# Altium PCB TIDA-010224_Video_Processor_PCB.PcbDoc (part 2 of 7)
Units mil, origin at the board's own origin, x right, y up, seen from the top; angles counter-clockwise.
Board outline 2355.46 x 4164 mil, 10 copper layers (L1-Top Layer, L2-GND, L3-SIG1, L4-GND, L5-PWR, L6-PWR, L7-GND, L8-SIG2, L9-GND, L10-Bottom Layer), stack 62.2 mil thick; 508 components, 274 nets, 3619 pads, 705 vias.
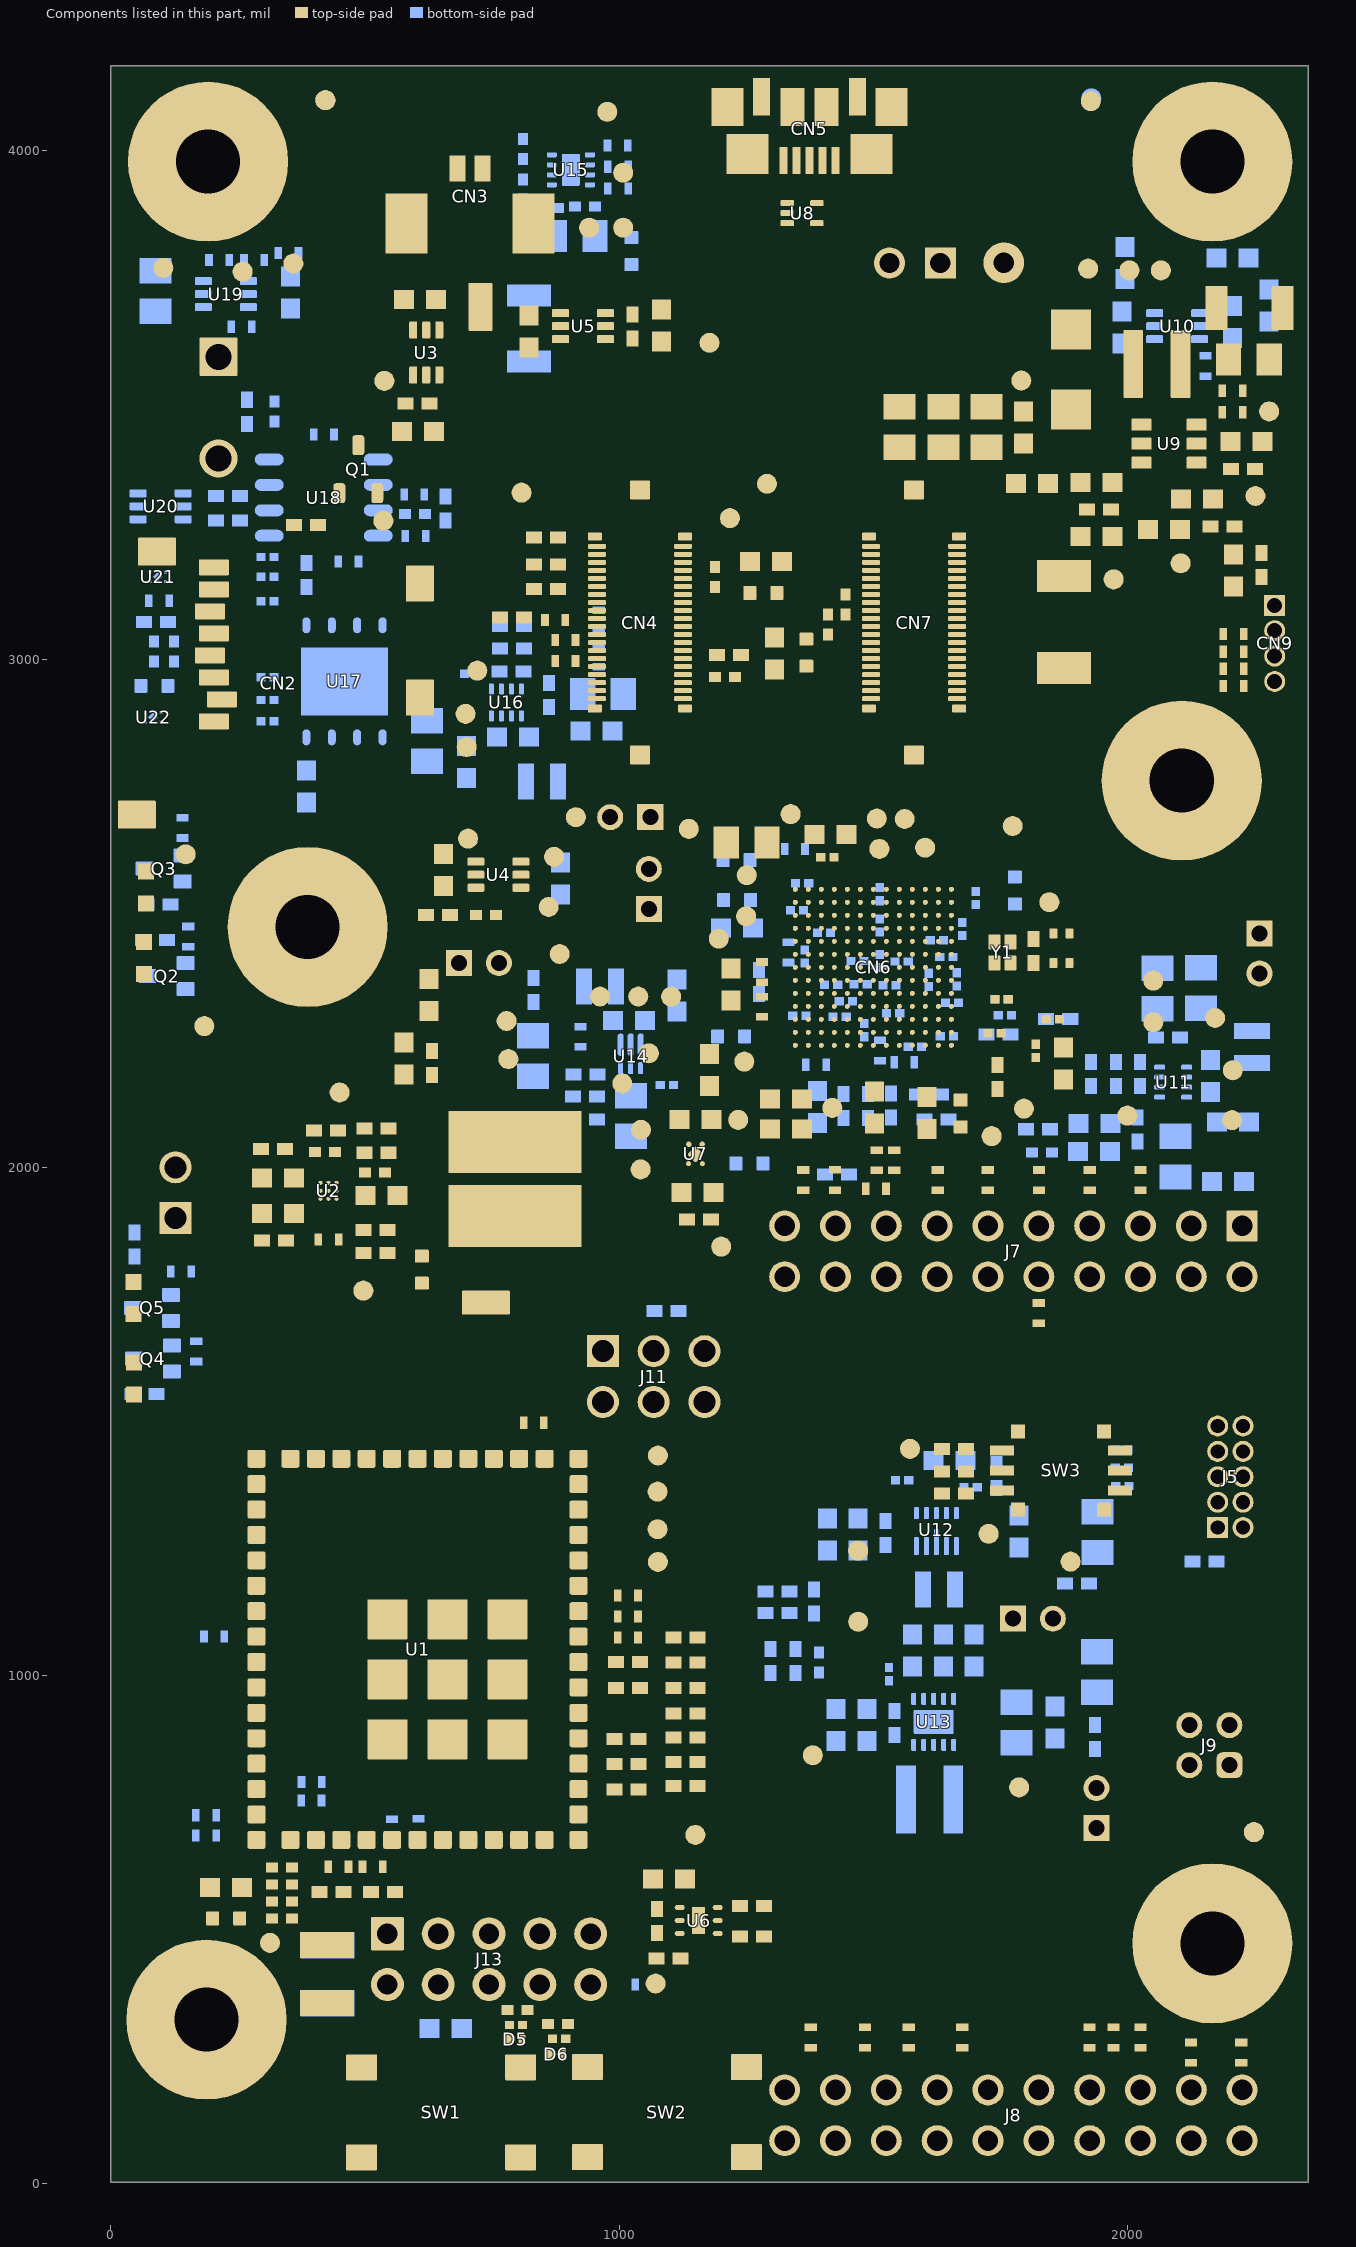
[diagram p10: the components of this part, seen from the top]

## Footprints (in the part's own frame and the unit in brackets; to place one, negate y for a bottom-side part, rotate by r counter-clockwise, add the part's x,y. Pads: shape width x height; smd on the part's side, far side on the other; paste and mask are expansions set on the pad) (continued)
2010 [mm] "Chip Capacitor, Body 5.08x2.54mm, IPC Medium Density"
  rect 1.6x2.7 smd: 1(-2.3,0) 2(2.3,0)
  silkscreen extent -3.42,-1.65 3.42,1.65, body extent -2.73,-1.45 2.73,1.45, height 1.66
0533980271 [mm] "Molex PicoBlade 2 pos from documents no. SD-53398-033 dated 2006-04-02"
  rect 0.8x1.3 smd: 1(-0.625,1.375) 2(0.625,1.375)
  rect 2.1x3 smd: 3(-3.175,-1.375) 4(3.175,-1.375)
  silkscreen extent -4.55,-3.17 4.57,2.29, body extent -3.86,-2.44 3.79,1.76, height 4.8
AssemblyNote [mil] "Assembly Note"
AssemblyNoteLabel [mil] "Assembly Note for PCB Labels"
BoosterPack_40pin_J1J3 [mm] "Receptacle, 2.54mm, 10x2, TH"
  rrect6% 1.55x1.55 hole 1.02: 1(1.27,11.43)
  round 1.55 hole 1.02: 2(1.27,8.89) 3(1.27,6.35) 4(1.27,3.81) 5(1.27,1.27) 6(1.27,-1.27) 7(1.27,-3.81) 8(1.27,-6.35) 9(1.27,-8.89) 10(1.27,-11.43) 21(-1.27,11.43) 22(-1.27,8.89) 23(-1.27,6.35) 24(-1.27,3.81) 25(-1.27,1.27) 26(-1.27,-1.27) 27(-1.27,-3.81) 28(-1.27,-6.35) 29(-1.27,-8.89) 30(-1.27,-11.43)
  silkscreen extent -2.48,-12.95 2.48,12.95, body extent -2.48,-12.95 2.48,12.95, height 8.51
BoosterPack_40pin_J2J4 [mm] "Receptacle, 2.54mm, 10x2, TH"
  round 1.55 hole 1.02: 11(-1.27,-11.43) 12(-1.27,-8.89) 13(-1.27,-6.35) 14(-1.27,-3.81) 15(-1.27,-1.27) 16(-1.27,1.27) 17(-1.27,3.81) 18(-1.27,6.35) 19(-1.27,8.89) 20(-1.27,11.43) 31(1.27,-11.43) 32(1.27,-8.89) 33(1.27,-6.35) 34(1.27,-3.81) 35(1.27,-1.27) 36(1.27,1.27) 37(1.27,3.81) 38(1.27,6.35) 39(1.27,8.89) 40(1.27,11.43)
  silkscreen extent -2.48,-12.95 2.48,12.95, body extent -2.48,-12.95 2.48,12.95, height 8.51
CE_Mark_5mm [mil] "Minimum text height for CE Mark"
  silkscreen extent -138,-98 138,98
CUI_CMA-6542TF-K [mil] "SMD, 2-Leads, Dia 9.9mm"
  rect 121.67x262.28 smd: 1(-72.65,0) 2(72.65,0)
  silkscreen extent -195,-195 195,195, body extent -191,-191 191,191, height 272
D0008A_N [mm] "SOIC, 8-Leads, Body 4.9x3.9mm, Pitch 1.27mm, IPC Medium Density"
  oval 1.45x0.6 smd: 1(-2.725,1.905) 2(-2.725,0.635) 3(-2.725,-0.635) 4(-2.725,-1.905) 5(2.725,-1.905) 6(2.725,-0.635) 7(2.725,0.635) 8(2.725,1.905)
  silkscreen extent -3.3,-2.5 0.9,2.5, body extent -3,-2.45 3,2.45, height 1.63
DBV0006A_N [mm] "SOT23, 6-Leads, Body 2.9x1.6mm, Pitch 0.95mm, Lead Span 2.8mm, IPC Medium Density"
  rrect17% 1x0.6 smd: 1(-1.375,0.95) 2(-1.375,0) 3(-1.375,-0.95) 4(1.375,-0.95) 5(1.375,0) 6(1.375,0.95)
  silkscreen extent -1.68,-1.55 0.5,1.55, body extent -1.42,-1.46 1.42,1.46, height 1.12
DCK0006A_N [mm] "SOT23, 6-Leads, Body 2x1.3mm, Pitch 0.65mm, Lead Span 2.1mm, IPC Medium Density"
  rrect25% 0.85x0.4 smd: 1(-1.125,0.65) 2(-1.125,0) 3(-1.125,-0.65) 4(1.125,-0.65) 5(1.125,0) 6(1.125,0.65)
  silkscreen extent -1.5,-1.09 0.51,1.09, body extent -1.14,-1 1.14,1, height 0.95
DFE201610E [mm] "MuRata"
  rect 0.8x1.8 smd: 1(0.8,0) 2(-0.8,0)
  body extent -1.1,-0.9 1.1,0.9, height 1
DLA0010A [mm] "VQFN-HR-10"
  rrect40% 0.6x0.25 smd: 1(-0.9,1) 2(-0.9,0.5) 3(-0.9,0) 4(-0.9,-0.5) 5(-0.9,-1)
  rrect40% 0.9x0.25 smd: 6(0.75,-1) 7(0.75,-0.5) 9(0.75,0.5) 10(0.75,1)
  rrect40% 1.3x0.25 smd paste-1: 8(0.55,0)
  silkscreen extent -1,-1.65 1,1.9, body extent -1,-1.5 1,1.5, height 1
DLC0008A [mm] "VSON-HR-8"
  rrect40% 0.55x0.25 smd: 1(-0.675,0.75) 2(-0.675,0.25) 3(-0.675,-0.25) 4(-0.675,-0.75) 5(0.675,-0.75) 6(0.675,-0.25) 7(0.675,0.25) 8(0.675,0.75)
  silkscreen extent -0.75,-1.15 0.75,1.15, body extent -0.8,-1.05 0.8,1.05, height 1.02
DMQ0006A [mm] "6-pin VSON"
  rrect40% 0.6x0.25 smd paste+0: 1(-0.65,0.5) 2(-0.65,0) 3(-0.65,-0.5)
  rrect67% 1.1x0.3 smd paste-0.15 mask-0.025: 4(0.52,-0.5) 5(0.525,0) 6(0.525,0.5)
  rrect50% 0.85x0.2 on Bottom Paste: 4(0.525,-0.5) 5(0.525,0) 6(0.525,0.5)
  silkscreen extent -0.75,-0.9 0.75,0.9, body extent -0.75,-0.75 0.75,0.75, height 1
DNP0006A [mm] "DFN-6 2x2mm"
  oval 0.5x0.25 smd: 1(-0.95,0.65) 2(-0.95,0) 3(-0.95,-0.655) 4(0.95,-0.65) 5(0.95,0) 6(0.95,0.65)
  rect 0.65x1.35 smd paste-0.5: 7(0,0)
  silkscreen extent -1.12,-1.15 1.12,1.15, body extent -1,-1 1,1, height 0.64
DPW0004A#1 [mm] "PX2SON"
  rect 0.15x0.15 smd mask+0.05: 1(-0.39,0.24) 2(-0.39,-0.24) 3(0.39,-0.24) 4(0.39,0.24)
  rect 0.35x0.35 smd rot 135 paste-0.055 mask-0.05: 5(0,0)
  L1-Top Layer region: -0.55,0.08 -0.588,0.088 -0.621,0.109 -0.642,0.142 -0.65,0.18 -0.65,0.18 -0.65,0.3 -0.642,0.338 -0.621,0.371 -0.588,0.392 -0.55,0.4 -0.55,0.4 -0.13,0.4 -0.13,0.269 -0.319,0.08
  L1-Top Layer region: 0.13,-0.4 0.13,-0.269 0.319,-0.08 0.55,-0.08 0.588,-0.088 0.621,-0.109 0.642,-0.142 0.65,-0.18 0.65,-0.18 0.65,-0.3 0.642,-0.338 0.621,-0.371 0.588,-0.392 0.55,-0.4 0.55,-0.4
  L1-Top Layer region: 0.319,0.08 0.13,0.269 0.13,0.4 0.55,0.4 0.588,0.392 0.621,0.371 0.642,0.338 0.65,0.3 0.65,0.3 0.65,0.18 0.642,0.142 0.621,0.109 0.588,0.088 0.55,0.08 0.55,0.08 0.55,0.08
  L1-Top Layer region: -0.55,-0.4 -0.588,-0.392 -0.621,-0.371 -0.642,-0.338 -0.65,-0.3 -0.65,-0.3 -0.65,-0.18 -0.642,-0.142 -0.621,-0.109 -0.588,-0.088 -0.55,-0.08 -0.55,-0.08 -0.319,-0.08 -0.13,-0.269 -0.13,-0.4
  silkscreen extent -0.6,-0.6 0.6,0.6, body extent -0.42,-0.42 0.42,0.42, height 0.41
DPW0004A#2 [mm] "PX2SON"
  rect 0.15x0.15 smd mask+0: 1(-0.39,0.24) 2(-0.39,-0.24) 3(0.39,-0.24) 4(0.39,0.24)
  rect 0.35x0.35 smd rot 135 paste-0.055 mask-0.05: 5(0,0)
  L1-Top Layer region: -0.55,-0.4 -0.588,-0.392 -0.621,-0.371 -0.642,-0.338 -0.65,-0.3 -0.65,-0.3 -0.65,-0.18 -0.642,-0.142 -0.621,-0.109 -0.588,-0.088 -0.55,-0.08 -0.55,-0.08 -0.319,-0.08 -0.13,-0.269 -0.13,-0.4
  L1-Top Layer region: 0.319,0.08 0.13,0.269 0.13,0.4 0.55,0.4 0.588,0.392 0.621,0.371 0.642,0.338 0.65,0.3 0.65,0.3 0.65,0.18 0.642,0.142 0.621,0.109 0.588,0.088 0.55,0.08 0.55,0.08 0.55,0.08
  L1-Top Layer region: 0.13,-0.4 0.13,-0.269 0.319,-0.08 0.55,-0.08 0.588,-0.088 0.621,-0.109 0.642,-0.142 0.65,-0.18 0.65,-0.18 0.65,-0.3 0.642,-0.338 0.621,-0.371 0.588,-0.392 0.55,-0.4 0.55,-0.4
  L1-Top Layer region: -0.55,0.08 -0.588,0.088 -0.621,0.109 -0.642,0.142 -0.65,0.18 -0.65,0.18 -0.65,0.3 -0.642,0.338 -0.621,0.371 -0.588,0.392 -0.55,0.4 -0.55,0.4 -0.13,0.4 -0.13,0.269 -0.319,0.08
  silkscreen extent -0.6,-0.6 0.6,0.6, body extent -0.42,-0.42 0.42,0.42, height 0.41
DPY0002A [mm] "X1SON-2"
  rrect57% 0.35x0.6 smd paste-0.5 mask-0.05: 1(-0.325,0) 2(0.325,0)
  rrect33% 0.3x0.5 on Top Paste: 1S(-0.35,0) 2S(0.35,0)
  silkscreen extent -0.85,-0.02 -0.8,0.02, body extent -0.5,-0.3 0.5,0.3, height 0.45
DQN0004A-MFG [mm] "SON, 0.65mm pitch"
  round 0.279 smd paste-1000 mask-1000: 1(-0.505,0.33) 2(-0.505,-0.33)
  round 0.251 smd paste-1000 mask-1000: 3(0.459,-0.346) 4(0.459,0.346)
  rrect17% 0.58x0.58 smd rot 135 paste-1000 mask-1000: 5(0,0)
  L1-Top Layer region: -0.66,0.485 -0.2,0.485 -0.2,0.385 -0.41,0.175 -0.66,0.175
  L1-Top Layer region: 0.66,-0.485 0.2,-0.485 0.2,-0.385 0.41,-0.175 0.66,-0.175
  L1-Top Layer region: 0.66,0.485 0.2,0.485 0.2,0.385 0.41,0.175 0.66,0.175
  L1-Top Layer region: -0.66,-0.485 -0.2,-0.485 -0.2,-0.385 -0.41,-0.175 -0.66,-0.175
  silkscreen extent -0.57,-0.9 0.53,1.4, body extent -0.76,-0.63 0.76,0.63, height 0.25
DRL0005A [mm] "SOTFL, 5-Flat Leads, Body 1.2x1.6x0.6mm, Pitch 0.5mm, TI recommended"
  rrect33% 0.67x0.3 smd: 1(-0.74,0.5) 2(-0.74,0) 3(-0.74,-0.5) 4(0.74,-0.5) 5(0.74,0.5)
  silkscreen extent -0.9,-0.95 0.5,0.95, body extent -0.85,-0.85 0.85,0.85, height 0.62
DSG0008A [mm] "SON, 8-Leads, Body 2x2mm, Pitch 0.5mm, Thermal Pad 1.6x0.9mm, TI Recommended"
  rrect40% 0.5x0.25 smd: 1(-0.95,0.75) 2(-0.95,0.25) 3(-0.95,-0.25) 4(-0.95,-0.75) 5(0.95,-0.75) 6(0.95,-0.25) 7(0.95,0.25) 8(0.95,0.75)
  rrect14% 0.9x0.7 on Bottom Paste: 9(0,-0.45) 9(0,0.45)
  rrect11% 0.9x1.6 smd paste-0.45: 9(0,0)
  silkscreen extent -1.07,-1.15 1.07,1.15, body extent -1,-1 1,1, height 0.77
DSK0010A [mm] "SON, 10-Leads, Body 2.5x2.5mm, Pitch 0.5mm, Thermal Pad 2x1.2mm - ADI"
  rrect40% 0.6x0.25 smd: 1(-1.15,1) 2(-1.15,0.5) 3(-1.15,0) 4(-1.15,-0.5) 5(-1.15,-1) 6(1.15,-1) 7(1.15,-0.5) 8(1.15,0) 9(1.15,0.5) 10(1.15,1)
  rrect11% 1.13x0.89 on Bottom Paste: 11(0,-0.545) 11(0,0.545)
  rrect8% 1.2x2 smd paste-0.6: 11(0,0)
  silkscreen extent -1.3,-1.45 1.3,1.45, body extent -1.25,-1.25 1.25,1.25, height 0.8
FCC_disclaimer [mil]
Fiducial10-20 [mm]
  round 1 smd mask+0.5: 1(0,0)
  L1-Top Layer keep-out circle w1.178: c0,0 r0.5
FP-8Q-24.000MEIV-T_SMD-4-MFG [mm]
  rrect17% 0.75x0.6 smd paste+0 mask+0: 1(-0.525,-0.4) 2(0.525,-0.4) 3(0.525,0.4) 4(-0.525,0.4)
  silkscreen extent -1.22,-1.19 1.22,0.67, body extent -1,-0.8 1,0.8, height 0.25
FP-430152070826_SMT_TACT-MFG [mm]
  rrect8% 1.55x1.3 smd paste+0 mask+0: 1(-3.975,2.25) 2(-3.975,-2.25) 3(3.975,2.25) 4(3.975,-2.25)
  silkscreen extent -5.47,-3.2 3.2,3.2, body extent -4.85,-3.3 4.85,3.3, height 0.25
FP-693071010811_CONN_SMT_MEMORY-MFG [mm]
  rrect13% 0.8x1.5 smd paste+0 mask+0: 1(1.94,-3.1) 2(0.84,-2.7) 3(-0.26,-3.1) 4(-1.36,-3.3) 5(-2.46,-3.1) 6(-3.56,-3.3) 7(-4.66,-3.1) 8(-5.76,-3.1)
  rrect7% 1.4x1.9 smd paste+0 mask+0: 9(-6.55,-5.95) 9(6.6,-6.95)
  rrect7% 1.8x1.4 smd paste+0 mask+0: 10(-4.95,7.2) 10(0.75,7.2)
  silkscreen extent -7.12,-8.11 7.12,7.7, body extent -7.35,-8 7.4,8, height 0.25
FP-BLM18KG121TN1D_0603-MFG [mm] "0603 from SM-752 data"
  rrect15% 0.65x0.7 smd paste+0 mask+0: 1(-0.675,0) 2(0.675,0)
  silkscreen extent -0.87,-0.8 0.87,0.8, body extent -1.1,-0.58 1.1,0.58, height 0.25
FP-GRM1555C1H8R2BA01D_0402-MFG [mm] "0402 from SM-752 data"
  rrect25% 0.4x0.5 smd paste+0 mask+0: 1(-0.4,0) 2(0.4,0)
  silkscreen extent -0.53,-0.65 0.53,0.65, body extent -0.7,-0.38 0.7,0.38, height 0.25
FP-NTS4001NT1G_SC-70-MFG [mm]
  rrect14% 0.9x0.7 smd paste+0 mask+0: 1(-0.95,0.65) 2(-0.95,-0.65) 3(0.95,0)
  silkscreen extent -0.13,-1.1 0.67,1.1, body extent -0.63,-1 0.63,1, height 1
FP-OA7000_BGA169-IPC_C [mm]
  round 0.255 smd paste+0 mask+0: A1(-3.9,3.9) A2(-3.25,3.9) A3(-2.6,3.9) A4(-1.95,3.9) A5(-1.3,3.9) A6(-0.65,3.9) A7(0,3.9) A8(0.65,3.9) A9(1.3,3.9) A10(1.95,3.9) A11(2.6,3.9) A12(3.25,3.9) A13(3.9,3.9) B1(-3.9,3.25) B2(-3.25,3.25) B3(-2.6,3.25) B4(-1.95,3.25) B5(-1.3,3.25) B6(-0.65,3.25) B7(0,3.25) B8(0.65,3.25) B9(1.3,3.25) B10(1.95,3.25) B11(2.6,3.25) B12(3.25,3.25) B13(3.9,3.25) C1(-3.9,2.6) C2(-3.25,2.6) C3(-2.6,2.6) C4(-1.95,2.6) C5(-1.3,2.6) C6(-0.65,2.6) C7(0,2.6) C8(0.65,2.6) C9(1.3,2.6) C10(1.95,2.6) C11(2.6,2.6) C12(3.25,2.6) C13(3.9,2.6) D1(-3.9,1.95) D2(-3.25,1.95) D3(-2.6,1.95) D4(-1.95,1.95) D5(-1.3,1.95) D6(-0.65,1.95) D7(0,1.95) D8(0.65,1.95) D9(1.3,1.95) D10(1.95,1.95) D11(2.6,1.95) D12(3.25,1.95) D13(3.9,1.95) E1(-3.9,1.3) E2(-3.25,1.3) E3(-2.6,1.3) E4(-1.95,1.3) E5(-1.3,1.3) E6(-0.65,1.3) E7(0,1.3) E8(0.65,1.3) E9(1.3,1.3) E10(1.95,1.3) E11(2.6,1.3) E12(3.25,1.3) E13(3.9,1.3) F1(-3.9,0.65) F2(-3.25,0.65) F3(-2.6,0.65) F4(-1.95,0.65) F5(-1.3,0.65) F6(-0.65,0.65) F7(0,0.65) F8(0.65,0.65) F9(1.3,0.65) F10(1.95,0.65) F11(2.6,0.65) F12(3.25,0.65) F13(3.9,0.65) G1(-3.9,0) G2(-3.25,0) G3(-2.6,0) G4(-1.95,0) G5(-1.3,0) G6(-0.65,0) G7(0,0) G8(0.65,0) G9(1.3,0) G10(1.95,0) G11(2.6,0) G12(3.25,0) G13(3.9,0) H1(-3.9,-0.65) H2(-3.25,-0.65) H3(-2.6,-0.65) H4(-1.95,-0.65) H5(-1.3,-0.65) H6(-0.65,-0.65) H7(0,-0.65) H8(0.65,-0.65) H9(1.3,-0.65) H10(1.95,-0.65) H11(2.6,-0.65) H12(3.25,-0.65) H13(3.9,-0.65) J1(-3.9,-1.3) J2(-3.25,-1.3) J3(-2.6,-1.3) J4(-1.95,-1.3) J5(-1.3,-1.3) J6(-0.65,-1.3) J7(0,-1.3) J8(0.65,-1.3) J9(1.3,-1.3) J10(1.95,-1.3) J11(2.6,-1.3) J12(3.25,-1.3) J13(3.9,-1.3) K1(-3.9,-1.95) K2(-3.25,-1.95) K3(-2.6,-1.95) K4(-1.95,-1.95) K5(-1.3,-1.95) K6(-0.65,-1.95) K7(0,-1.95) K8(0.65,-1.95) K9(1.3,-1.95) K10(1.95,-1.95) K11(2.6,-1.95) K12(3.25,-1.95) K13(3.9,-1.95) L1(-3.9,-2.6) L2(-3.25,-2.6) L3(-2.6,-2.6) L4(-1.95,-2.6) L5(-1.3,-2.6) L6(-0.65,-2.6) L7(0,-2.6) L8(0.65,-2.6) L9(1.3,-2.6) L10(1.95,-2.6) L11(2.6,-2.6) L12(3.25,-2.6) L13(3.9,-2.6) M1(-3.9,-3.25) M2(-3.25,-3.25) M3(-2.6,-3.25) M4(-1.95,-3.25) M5(-1.3,-3.25) M6(-0.65,-3.25) M7(0,-3.25) M8(0.65,-3.25) M9(1.3,-3.25) M10(1.95,-3.25) M11(2.6,-3.25) M12(3.25,-3.25) M13(3.9,-3.25) N1(-3.9,-3.9) N2(-3.25,-3.9) N3(-2.6,-3.9) N4(-1.95,-3.9) N5(-1.3,-3.9) N6(-0.65,-3.9) N7(0,-3.9) N8(0.65,-3.9) N9(1.3,-3.9) N10(1.95,-3.9) N11(2.6,-3.9) N12(3.25,-3.9) N13(3.9,-3.9)
  silkscreen extent -5.55,-5 5,5, body extent -5.1,-5.1 5.1,5.1, height 0.25
FP-XAL4030-472MEC_SMD2-MFG [mm]
  rrect10% 0.98x3.4 smd paste+0 mask+0: 1(-1.185,0) 2(1.185,0)
  silkscreen extent -2.15,-2.15 2.15,2.15, body extent -2,-2 2,2, height 3.1
Harwin_M22-2510205 [mm] "Header, 2mm, 2x1, TH"
  rect 1.3x1.3 hole 0.8: 1(-1,0)
  round 1.3 hole 0.8: 2(1,0)
  silkscreen extent -2,-1.5 2,1, body extent -2,-1 2,1, height 5
Hirose_FX12B-40P-0_4SV [mm] "Plug, 0.4 mm, 20x2, SMT"
  rrect43% 0.9x0.23 smd paste-0.23: 1(-2.15,3.8) 2(2.15,3.8) 3(-2.15,3.4) 4(2.15,3.4) 5(-2.15,3) 6(2.15,3) 7(-2.15,2.6) 8(2.15,2.6) 9(-2.15,2.2) 10(2.15,2.2) 11(-2.15,1.8) 12(2.15,1.8) 13(-2.15,1.4) 14(2.15,1.4) 15(-2.15,1) 16(2.15,1) 17(-2.15,0.6) 18(2.15,0.6) 19(-2.15,0.2) 20(2.15,0.2) 21(-2.15,-0.2) 22(2.15,-0.2) 23(-2.15,-0.6) 24(2.15,-0.6) 25(-2.15,-1) 26(2.15,-1) 27(-2.15,-1.4) 28(2.15,-1.4) 29(-2.15,-1.8) 30(2.15,-1.8) 31(-2.15,-2.2) 32(2.15,-2.2) 33(-2.15,-2.6) 34(2.15,-2.6) 35(-2.15,-3) 36(2.15,-3) 37(-2.15,-3.4) 38(2.15,-3.4) 39(-2.15,-3.8) 40(2.15,-3.8)
  rrect25% 0.7x0.4 smd paste-0.23: MP1(-2.25,4.3) MP2(2.25,4.3) MP3(-2.25,-4.3) MP4(2.25,-4.3)
  rrect11% 1x0.95 smd paste-1: MP5(0,6.625) MP6(0,-6.625)
  rrect33% 0.7x0.3 on Top Paste paste-0.23: ""(-2.25,-4.3) ""(-2.25,4.3) ""(2.25,-4.3) ""(2.25,4.3)
  rrect50% 0.9x0.2 on Top Paste paste-0.23: ""(-2.15,-3.8) ""(-2.15,-3.4) ""(-2.15,-3) ""(-2.15,-2.6) ""(-2.15,-2.2) ""(-2.15,-1.8) ""(-2.15,-1.4) ""(-2.15,-1) ""(-2.15,-0.6) ""(-2.15,-0.2) ""(-2.15,0.2) ""(-2.15,0.6) ""(-2.15,1) ""(-2.15,1.4) ""(-2.15,1.8) ""(-2.15,2.2) ""(-2.15,2.6) ""(-2.15,3) ""(-2.15,3.4) ""(-2.15,3.8) ""(2.15,-3.8) ""(2.15,-3.4) ""(2.15,-3) ""(2.15,-2.6) ""(2.15,-2.2) ""(2.15,-1.8) ""(2.15,-1.4) ""(2.15,-1) ""(2.15,-0.6) ""(2.15,-0.2) ""(2.15,0.2) ""(2.15,0.6) ""(2.15,1) ""(2.15,1.4) ""(2.15,1.8) ""(2.15,2.2) ""(2.15,2.6) ""(2.15,3) ""(2.15,3.4) ""(2.15,3.8)
  rrect11% 0.9x0.95 on Top Paste paste-0.23: ""(0,-6.625) ""(0,6.625)
  body extent -2.45,-6.89 2.45,6.9, height 1.34
Hirose_ZX62R-B-5P [mm] "Hirose"
  rect 1.35x0.4 smd: 1(-2.68,1.3) 2(-2.68,0.65) 3(-2.68,0) 4(-2.68,-0.65) 5(-2.68,-1.3)
  rect 2x2.1 smd: 6(-2.35,-3.1) 7(-2.35,3.1)
  rect 1.9x1.6 smd: 8(0,-4.1) 13(0,4.1)
  rect 1.88x0.85 smd: 9(0.495,-2.4) 12(0.495,2.4)
  rect 1.9x1.2 smd: 10(0,-0.85) 11(0,0.85)
  silkscreen extent -4,-3.67 1.7,3.67, body extent -2.57,-3.48 2.11,3.45, height 2.65
Keystone5000 [mil] "For Keystone 500x miniature loop terminals"
  round 80 hole 40: 1(0,0)
  silkscreen extent -52,-52 52,52, body extent -49,-49 49,49, height 182
Keystone_1902C [mil] "Hex Standoff, 4-40 threaded, nylon"
  round 1 on Mech4: 0(0,0)
  body extent -145,-126 146,126, height 501
Label_650x200 [mil] "Thermal Transfer Label"
  round 1 on Mech14: 0(0,0)
  silkscreen extent -325,-100 325,100, body extent -325,-100 325,100, height 1
MON0063A [mm] "QFM"
  rrect22% 0.9x0.9 smd paste-0.05 mask+0.05: 1(-11.774,9.524) 2(-11.774,8.255) 3(-11.774,6.985) 4(-11.774,5.715) 5(-11.774,4.445) 6(-11.774,3.175) 7(-11.774,1.905) 8(-11.774,0.635) 9(-11.774,-0.635) 10(-11.774,-1.905) 11(-11.774,-3.175) 12(-11.774,-4.445) 13(-11.774,-5.715) 14(-11.774,-6.985) 15(-11.774,-8.255) 16(-11.774,-9.524) 17(-10.074,-9.524) 18(-8.804,-9.524) 19(-7.534,-9.524) 20(-6.264,-9.524) 21(-4.994,-9.524) 22(-3.724,-9.524) 23(-2.454,-9.524) 24(-1.184,-9.524) 25(0.086,-9.524) 26(1.356,-9.524) 27(2.626,-9.524) 28(4.326,-9.524) 29(4.326,-8.255) 30(4.326,-6.985) 31(4.326,-5.715) 32(4.326,-4.445) 33(4.326,-3.175) 34(4.326,-1.905) 35(4.326,-0.635) 36(4.326,0.635) 37(4.326,1.905) 38(4.326,3.175) 39(4.326,4.445) 40(4.326,5.715) 41(4.326,6.985) 42(4.326,8.255) 43(4.326,9.524) 44(2.626,9.524) 45(1.356,9.524) 46(0.086,9.524) 47(-1.184,9.524) 48(-2.454,9.524) 49(-3.724,9.524) 50(-4.994,9.524) 51(-6.264,9.524) 52(-7.534,9.524) 53(-8.804,9.524) 54(-10.074,9.524)
  rrect11% 0.89x0.89 on Top Paste: 55(-8.774,3.95) 55(-7.674,3.95) 56(-8.774,0.95) 56(-8.774,2.05) 56(-7.674,0.95) 56(-7.674,2.05) 57(-8.774,-2.05) 57(-8.774,-0.95) 57(-7.674,-2.05) 57(-7.674,-0.95) 58(-5.774,3.95) 58(-5.774,5.05) 58(-4.674,3.95) 58(-4.674,5.05) 59(-5.774,0.95) 59(-5.774,2.05) 59(-4.674,0.95) 59(-4.674,2.05) 60(-5.774,-2.05) 60(-5.774,-0.95) 60(-4.674,-2.05) 60(-4.674,-0.95) 61(-2.774,5.05) 61(-2.774,3.95) 61(-1.674,5.05) 61(-1.674,3.95) 62(-2.774,2.05) 62(-2.774,0.95) 62(-1.674,2.05) 62(-1.674,0.95) 63(-2.774,-0.95) 63(-2.774,-2.05) 63(-1.674,-0.95) 63(-1.674,-2.05)
  rrect5% 2x2 smd paste-1 mask-1: 55(-8.224,4.5)
  rrect5% 2x2 smd paste-1 mask+0: 56(-8.224,1.5) 57(-8.224,-1.5) 58(-5.224,4.5) 59(-5.224,1.5) 60(-5.224,-1.5) 61(-2.224,4.5) 62(-2.224,1.5) 63(-2.224,-1.5)
  L1-Top Layer region: -9.274,-2.45 -9.274,5.45 -9.266,5.488 -9.245,5.521 -9.212,5.542 -9.174,5.55 -9.174,5.55 -1.274,5.55 -1.236,5.542 -1.203,5.521 -1.182,5.488 -1.174,5.45 -1.174,5.45 -1.174,-2.45 -1.182,-2.488 -1.203,-2.521 -1.236,-2.542 -1.274,-2.55 -1.274,-2.55 -9.174,-2.55 -9.212,-2.542 -9.245,-2.521 -9.266,-2.488 -9.274,-2.45
  silkscreen extent -12.75,-10.5 12.75,10.5, body extent -12.5,-10.25 12.5,10.25, height 2.32
"NY PMS 440 0025 PH" [mm] "4-40 nylon screw and mounting hole"
  round 8 hole 3.2: 1(0,0)
  body extent -3.3,-3.3 3.3,3.3, height 2.69
PhoenixContact_1715721 [mm] "Phoenix Contact 1715721 used on LM3445 design from Longmont"
  rrect5% 1.905x1.905 hole 1.3: 1(-2.54,0)
  round 1.9 hole 1.3: 2(2.54,0)
  silkscreen extent -5.82,-5.25 5.08,5.2, body extent -5.82,-4.6 5.08,5.2, height 14.2
Samtec_FTSH-105-01-x-D-K [mm] "Header, 1.27 mm, 5x2, TH"
  rect 1.05x1.05 hole 0.71: 1(-0.635,2.54)
  round 1.05 hole 0.71: 2(0.635,2.54) 3(-0.635,1.27) 4(0.635,1.27) 5(-0.635,0) 6(0.635,0) 7(-0.635,-1.27) 8(0.635,-1.27) 9(-0.635,-2.54) 10(0.635,-2.54)
  silkscreen extent -2.54,-3.17 2.54,3.2, body extent -2.54,-3.17 2.54,3.1, height 5.73
SMA [mm] "Molded Diode, 2-Leads, Body 4.3x2.6mm, IPC Medium Density, based on OnSemi component dimensions and land pattern"
  rect 2x2 smd: 1(-2,0) 2(2,0)
  silkscreen extent -3.66,-1.57 2.79,1.57, body extent -2.6,-1.3 2.6,1.3, height 2.42
SOT-23 [mm] "SOT23, 3-Leads, Body 2.9x1.3mm, Pitch 0.95mm, Lead Span 2.5mm, IPC Medium Density"
  rrect50% 1x0.6 smd: 1(-1.2,0.95) 2(-1.2,-0.95) 3(1.2,0)
  silkscreen extent -1.62,-1.5 0.7,1.5, body extent -1.16,-1.45 1.21,1.45, height 1
Sullins_GRPB041VWVN-RC [mm] "TH, Header, 1.27 mm, 4x1, Straight"
  rect 1.05x1.05 hole 0.75: 1(-1.905,0)
  round 1.05 hole 0.75: 2(-0.635,0) 3(0.635,0) 4(1.905,0)
  silkscreen extent -3.29,-1.07 2.79,1.07, body extent -2.79,-1.07 2.79,1.07, height 4.3
Sullins_PxC01DAAN [mm] "Header, 2.54mm, 1x2, TH"
  rect 1.55x1.55 hole 1.016: 1(-1.27,0)
  round 1.55 hole 1.016: 2(1.27,0)
  silkscreen extent -2.9,-1.53 2.61,1.53, body extent -2.61,-1.53 2.61,1.53, height 8.71
SW_CVS-03B [mm] "Copal Electronics"
  rect 1.2x0.5 smd: 1(-2.95,1) 2(-2.95,0) 3(-2.95,-1) 4(2.95,-1) 5(2.95,0) 6(2.95,1)
  rect 0.7x0.7 smd: M1(-2.15,1.95) M2(-2.15,-1.95) M3(2.15,-1.95) M4(2.15,1.95)
  silkscreen extent -3.71,-2 1.4,2, body extent -2.15,-2 2.15,2, height 1.45
TE_RCU [mm] "SMD, 1-Leads, Body 1.6x0.8mm"
  rrect8% 2.4x1.2 smd: 1(0,0)
  body extent -0.8,-0.45 0.8,0.45, height 1.15
TEC_282834-2 [mm] "TEC"
  rect 1.6x1.6 hole 1.1: 1(-1.27,0)
  round 1.6 hole 1.1: 2(1.27,0)
  silkscreen extent -3.66,-3.4 2.9,3.4, body extent -2.77,-3.25 2.77,3.25, height 10.01
TI_Stacked_Overlay_Small [mil]
  silkscreen extent -418,-98 418,98
TP_SM_1MM [mm] "1mm Test Point, SMT"
  round 1 smd paste-0.5: 1(0,0)
TSW-105-07-G-D [mm] "Samtec 100mil, 2x5, 230 mil above insulator"
  rrect6% 1.65x1.65 hole 1.016: 1(-5.08,-1.27)
  round 1.65 hole 1.016: 2(-5.08,1.27) 3(-2.54,-1.27) 4(-2.54,1.27) 5(0,-1.27) 6(0,1.27) 7(2.54,-1.27) 8(2.54,1.27) 9(5.08,-1.27) 10(5.08,1.27)
  silkscreen extent -6.35,-3.1 6.35,2.54, body extent -6.35,-2.54 6.35,2.54, height 8.38
WEEE_Minimum [mil] "WEEElie bin"
  silkscreen extent -95,-172 99,104
"Winbond-WSON6x5_Code P" [mm] "Winbond recommended land pattern"
  oval 0.8x0.4 smd: 1(-2.8,1.905) 2(-2.8,0.635) 3(-2.8,-0.635) 4(-2.8,-1.905) 5(2.8,-1.905) 6(2.8,-0.635) 7(2.8,0.635) 8(2.8,1.905)
  rect 3.4x4.35 smd: 9(0,0)
  silkscreen extent -3.84,-2.65 3.15,2.9, body extent -3.05,-2.55 3.05,2.55, height 0.8
WL-SMCW_Blue [mm] "SMD, 2-Leads, Body 1.6x0.8mm"
  rect 0.8x0.8 smd: 1(-0.8,0) 2(0.8,0)
  silkscreen extent -1.9,-0.8 1.2,0.8, body extent -0.85,-0.45 0.85,0.45, height 0.8
WL-SMCW_GREEN [mm] "WURTH"
  rect 0.8x0.8 smd: 1(-0.8,0) 2(0.8,0)
  silkscreen extent -1.9,-0.8 1.2,0.8, body extent -0.85,-0.45 0.85,0.45, height 0.8
WL-SMCW_RED [mm] "WURTH"
  rect 0.8x0.8 smd: 1(-0.8,0) 2(0.8,0)
  silkscreen extent -1.9,-0.8 1.2,0.8, body extent -0.85,-0.45 0.85,0.45, height 0.8
WL-SMCW_YELLOW [mm] "WURTH"
  rect 0.8x0.8 smd: 1(-0.8,0) 2(0.8,0)
  silkscreen extent -1.9,-0.8 1.2,0.8, body extent -0.85,-0.45 0.85,0.45, height 0.8
Wurth_61300621121 [mm] "Header, 2.54mm, 3x2, TH"
  rect 1.6x1.6 hole 1.1: 1(-1.27,2.54)
  round 1.6 hole 1.1: 2(1.27,2.54) 3(-1.27,0) 4(1.27,0) 5(-1.27,-2.54) 6(1.27,-2.54)
  silkscreen extent -2.8,-3.82 2.54,3.8, body extent -2.54,-3.82 2.54,3.8, height 7.27
XFL4020 [mm] "Coilcraft XFL4020 7/18/12"
  rect 0.98x3.4 smd: 1(-1.181,0) 2(1.181,0)
  silkscreen extent -2.16,-2.16 2.16,2.16, body extent -2.15,-2.15 2.15,2.15, height 2.1
YFF0009AAAC [mm] "BGA, 9-Balls, Body 1.214x1.16mm, Pitch 0.4mm"
  round 0.2 smd: A1(-0.4,0.4) A2(0,0.4) A3(0.4,0.4) B1(-0.4,0) B2(0,0) B3(0.4,0) C1(-0.4,-0.4) C2(0,-0.4) C3(0.4,-0.4)
  silkscreen extent -0.76,0.64 -0.66,0.73, body extent -0.61,-0.58 0.61,0.58, height 0.63

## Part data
1.1V 1.8V 1.35V 2.5V 3.3V 3.3V_MCU 3.3V_SC AOL AOM AVDD BAT C CLK D DBG0 DBG1 DI DO DVDD EN EN_1.35V FB FLASH_CLK FLASH_CS FLASH_MISO FLASH_MOSI FREQ ID IN1 IN2 IN_1.1V IN_1.8V IN_1.35V IN_2.5V IN_3.3V IN_PS IR_EN IR_IN1 IR_IN2 LED_EN LED_OUT LR MBIAS MCLK MEAS MEAS_EN MEAS_MCU MIC_IN ON OUT_PS OV_1.1V OV_1.8V OV_1.35V OV_3.3V PG_1.1V PG_1.8V PG_1.35V PG_3.3V PS_VCC PWR_EN REF RST SHDN SID SYSON1 SYSON2 USB VCC_ALS VCC_AMP VCC_IR VCC_MEM VDDAO VeFuse VMID VOUT1 VOUT2 VP VREF VREF_AU: library part CMP-0003825-1, "1mm Test Point, SMT", Manufacturer=Any
3.3V_PA VBAT: library part CMP-0067620-1, "PC Test Point, SMT", Manufacturer="TE Connectivity", Supplier Part Number 1=A106145CT-ND
C1 C2: library part CMP-0006638-2, "CAP, CERM, 1000 pF, 16 V, +/- 10%, X7R, 0402", Cap_Case=0402, Manufacturer=MuRata, Supplier Part Number 1=GRM155R71C102KA01D-ND, TempCo=X7R, Tolerance_%=10%, Value1=Unknown, Value2=16V, ValueDisplayed=1000pF
C3 C4 C5 C6 C8 C12 C19 C20 C22 C29 C30 C40 C41 C71 C103 C126 C130 C131 C134: library part Cap, "CAP CER 0.1UF 16V 10% X7R 0402", Manufacturer="Murata Electronics North America"
C7 C127: library part CMP-0009081-1, "CAP, CERM, 100 uF, 16 V, +/- 20%, X5R, 1210", Cap_Case=1210, Manufacturer=Kemet, Supplier Part Number 1=399-11270-1-ND, TempCo=X5R, Tolerance_%=20%, Value1=Unknown, Value2=16V, ValueDisplayed=100uF
C9 C34 C37 C38 C109: library part CMP-0064936-4, "CAP, CERM, 4.7 uF, 16 V,+/- 10%, X7R, 0603", Cap_Case=0603, Manufacturer=MuRata, TempCo=X7R, Tolerance_%=10%, Value1=Unknown, Value2=16V, ValueDisplayed=4.7uF
C10 C11: library part CMP-0006650-2, "CAP, CERM, 0.033 uF, 16 V, +/- 10%, X7R, 0402", Cap_Case=0402, Manufacturer=MuRata, Supplier Part Number 1=490-3257-1-ND, TempCo=X7R, Tolerance_%=10%, Value1=Unknown, Value2=16V, ValueDisplayed=0.033uF
C13 C14 C15 C18 C21 C24 C25 C26 C27 C33 C49 C52 C56 C59 C60 C61 C62 C66 C102 C117 C128 C129: library part CMP-0007137-1, "CAP, CERM, 1 uF, 16 V, +/- 20%, X7R, AEC-Q200 Grade 1, 0603", Cap_Case=0603, Manufacturer=MuRata, Supplier Part Number 1=81-GCM188R71C105MA4D, TempCo=X7R, Tolerance_%=20%, Value1=Unknown, Value2=16V, ValueDisplayed=1uF
C16 C23: library part CMP-0006228-1, "CAP, CERM, 0.1 uF, 16 V, +/- 10%, X7R, 0402", Cap_Case=0402, Manufacturer="Wurth Elektronik", Supplier Part Number 1=732-7532-1-ND, TempCo=X7R, Tolerance_%=10%, Value1=Unknown, Value2=16V, ValueDisplayed=0.1uF
C17 C35 C36 C42 C44: library part CMP-0007499-1, "CAP, CERM, 2.2 uF, 16 V, +/- 10%, X7R, 0603", Cap_Case=0603, Manufacturer=MuRata, Supplier Part Number 1=81-GRM188Z71C225KE3D, TempCo=X7R, Tolerance_%=10%, Value1=Unknown, Value2=16V, ValueDisplayed=2.2uF
C28: library part CMP-0006250-2, "CAP, CERM, 33 pF, 50 V, +/- 5%, C0G/NP0, 0402", Cap_Case=0402, Manufacturer=TDK, Supplier Part Number 1=445-13798-1-ND?, TempCo=C0G/NP0, Tolerance_%=5%, Value1=Unknown, Value2=50V, ValueDisplayed=33pF
C31 C43 C45 C46 C58 C133: library part CMP-0007995-1, "CAP, CERM, 10 uF, 16 V, +/- 10%, X7R, 0805", Cap_Case=0805, Manufacturer="Samsung Electro-Mechanics", Supplier Part Number 1=?1276-2872-6-ND?, TempCo=X7R, Tolerance_%=10%, Value1=Unknown, Value2=16V, ValueDisplayed=10uF
C39 C47 C48 C50 C51 C74 C75 C76 C77 C78 C79 C80 C81 C82 C83 C84 C85 C86 C88 C90 C91 C92 C94 C96 C97 C98 C99 C100 C101 C105 C106 C107 C108: library part CMP-0064970-1, "CAP, CERM, 0.1 uF, 16 V,+/- 10%, X7R, 0201", Cap_Case=0201, Manufacturer=MuRata, Supplier Part Number 1=81-GRM033Z71C104KE4D, TempCo=X7R, Tolerance_%=10%, Value1=Unknown, Value2=16V, ValueDisplayed=0.1uF
C53 C54: library part CMP-0089999-1, "8.2pF ±0.1pF 50V Ceramic Capacitor C0G, NP0 0402 (1005 Metric)", Digikey Part Number=490-6255-1-ND, Manufacturer="Murata Electronics North America", Mouser Part Number=81-GRM1555C1H8R2BA1D, Operating Temperature Range="-55°C to +125°C", TempCo=30ppm/°C, Temperature Characteristic=C0G, ValueDisplayed=8.2pF
C55: library part CMP-0064916-2, "CAP, CERM, 10 pF, 50 V,+/- 1%, C0G/NP0, 0402", Cap_Case=0402, Manufacturer=MuRata, Supplier Part Number 1=490-6186-1-ND, TempCo=C0G/NP0, Tolerance_%=1%, Value1=Unknown, Value2=50V, ValueDisplayed=10pF
C57 C119: library part CMP-0009154-2, "CAP, CERM, 22 uF, 16 V, +/- 20%, X7R, AEC-Q200 Grade 1, 1210", Cap_Case=1210_280, Manufacturer=TDK, Supplier Part Number 1=445-5723-1-ND, TempCo=X7R, Tolerance_%=20%, Value1="0.002582 ohm", Value2=16V, ValueDisplayed=22uF
C63 C110 C121: library part CMP-0007058-4, "CAP, CERM, 4.7 uF, 10 V, +/- 10%, X7S, 0603", Cap_Case=0603, Manufacturer=TDK, Supplier Part Number 1=445-14258-1-ND, TempCo=X7S, Tolerance_%=10%, Value1=Unknown, Value2=10V, ValueDisplayed=4.7uF
C64: library part CMP-0008302-2, "CAP, CERM, 10 uF, 25 V, +/- 10%, X5R, 0805", Cap_Case=0805, Manufacturer=MuRata, Supplier Part Number 1=490-5523-1-ND, TempCo=X5R, Tolerance_%=10%, Value1=Unknown, Value2=25V, ValueDisplayed=10uF
C65 C67 C68 C111 C120: library part CMP-0078699-1, "CAP, CERM, 47 µF, 10 V,+/- 20%, X5R, 0805", Cap_Case=0805, Manufacturer=MuRata, Supplier Part Number 1=490-9961-1-ND, TempCo=X5R, Tolerance_%=20%, Value2=10V, ValueDisplayed=47µF
C69 C114 C122: library part CMP-0006417-2, "CAP, CERM, 120 pF, 50 V, +/- 5%, C0G/NP0, 0402", Cap_Case=0402, Manufacturer=MuRata, Supplier Part Number 1=490-1292-1-ND, TempCo=C0G/NP0, Tolerance_%=5%, Value1=Unknown, Value2=50V, ValueDisplayed=120pF
C70: library part CMP-0081159-1, "CAP, CERM, 22 µF, 16 V,+/- 20%, X5R, 0603", Cap_Case=0603, Manufacturer=Samsung, Supplier Part Number 1=1276-7076-1-ND, TempCo=X5R, Tolerance_%=20%, Value2=16V, ValueDisplayed=22µF
C72 C113: library part CMP-0007995-1, "CAP, CERM, 10 uF, 16 V, +/- 10%, X7R, 0805", Cap_Case=0805, Manufacturer="Samsung Electro-Mechanics", TempCo=X7R, Tolerance_%=10%, Value1=Unknown, Value2=16V, ValueDisplayed=10uF
C73: library part CMP-0007005-5, "CAP, CERM, 22 uF, 10 V, +/- 20%, X5R, 0603", Cap_Case=0603, Manufacturer=TDK, Supplier Part Number 1=445-9077-1-ND, TempCo=X5R, Tolerance_%=20%, Value1="0.00371 ohm", Value2=10V, ValueDisplayed=22uF
C87 C89: library part CMP-0078507-1, "CAP, CERM, 4.7 µF, 16 V,+/- 20%, X5R, 0402", Cap_Case=0402, Manufacturer="Yageo America", Supplier Part Number 1=311-3482-1-ND, TempCo=X5R, Tolerance_%=20%, Value2=16V, ValueDisplayed=4.7µF
C93: library part CMP-0007303-5, "CAP, CERM, 10 uF, 6.3 V, +/- 20%, X5R, 0603", Cap_Case=0603, Manufacturer=MuRata, Supplier Part Number 1=490-3896-1-ND, TempCo=X5R, Tolerance_%=20%, Value1="0.009 ohm", Value2=6.3V, ValueDisplayed=10uF
C95: library part CMP-0007306-5, "CAP, CERM, 22 uF, 6.3 V, +/- 20%, X5R, 0603", Cap_Case=0603, Manufacturer=MuRata, Supplier Part Number 1=490-7611-1-ND, TempCo=X5R, Tolerance_%=20%, Value1=Unknown, Value2=6.3V, ValueDisplayed=22uF
C104: library part CMP-0006624-1, "CAP, CERM, 1 uF, 6.3 V, +/- 20%, X7R, 0402", Cap_Case=0402, Manufacturer=MuRata, Supplier Part Number 1=490-9665-1-ND, TempCo=X7R, Tolerance_%=20%, Value1=Unknown, Value2=6.3V, ValueDisplayed=1uF
C112: library part CMP-0007299-5, "CAP, CERM, 10 uF, 4 V, +/- 20%, X5R, 0603", Cap_Case=0603, Manufacturer=MuRata, Supplier Part Number 1=490-3298-1-ND, TempCo=X5R, Tolerance_%=20%, Value1="0.003 ohm", Value2=4V, ValueDisplayed=10uF
C115 C118 C123 C124: library part Cap, "CAP CER 0.1UF 16V 10% X7R 0402", Manufacturer="Murata Electronics North America", MFG Part Number=GRM155R71C104KA88D
C116: library part CMP-0006528-2, "CAP, CERM, 10 uF, 4 V, +/- 20%, X5R, 0402", Cap_Case=0402, Manufacturer=MuRata, Supplier Part Number 1=GRM155R60G106ME44D-ND, TempCo=X5R, Tolerance_%=20%, Value1=Unknown, Value2=4V, ValueDisplayed=10uF
C125: library part CMP-0006412-1, "CAP, CERM, 1000 pF, 50 V, +/- 5%, C0G/NP0, 0402", Cap_Case=0402, Manufacturer=MuRata, Supplier Part Number 1=490-3244-1-ND, TempCo=C0G/NP0, Tolerance_%=5%, Value1=Unknown, Value2=50V, ValueDisplayed=1000pF
C132: library part CMP-0006215-2, "CAP, CERM, 10 pF, 50 V, +/- 5%, C0G/NP0, 0402", Cap_Case=0402, Manufacturer="Wurth Elektronik", Supplier Part Number 1=732-7469-1-ND, TempCo=C0G/NP0, Tolerance_%=5%, Value1=Unknown, Value2=50V, ValueDisplayed=10pF
CN1: library part CMP-0054974-1, "Terminal Block, 2x1, 2.54mm, TH", Manufacturer="TE Connectivity", Supplier Part Number 1=A98333-ND
CN2: library part CMP-0089421-1, "9 (8 + 1) Position Card Connector Secure Digital - microSD™ Surface Mount, Right Angle Gold", Current_A=500mA, Digikey Part Number=732-3819-1-ND, Manufacturer="Wurth Electronics", Mouser Part Number=710-693071010811, Operating Temperature Range="-25°C to +85°C", Voltage_V=100V
CN3: library part CMP-0055117-1, "Plug, SMT, Vertical, 1.25mm, 1x2", Manufacturer=Molex, Supplier Part Number 1=WM7606CT-ND
CN4 CN7: library part CMP-0079908-1, "Plug, 0.4 mm, 20x2, Gold, SMT", Color=Black, Manufacturer="Hirose Electric Co. Ltd.", Supplier Part Number 1=H11407CT-ND
CN5: library part CMP-0079906-1, "Connector, Receptacle, Micro-USB Type B, Top Mount SMT", Color=Silver, Current_A=1.8A, Manufacturer="Hirose Electric Co. Ltd.", Supplier Part Number 1=H125274CT-ND, Voltage_V=30V
CN6: library part CMP-0089425-1, "Camera Video Processor", Manufacturer=Omnivision, Max Supply Voltage=3.6V, Min Supply Voltage=1.045V, Nominal Supply Current=233mA, Operating Temperature Range="-30°C to +85°C"
CN8: library part CMP-0054594-1, "Header, 2.54mm, 1x2, Tin, Black, TH", Color=Black, Current_A=3A, Manufacturer="Sullins Connector Solutions", Supplier Part Number 1=S2012E-01-ND, Voltage_V=1.8kV
CN9: "Header, 50mil, 4x1, Gold, TH", Manufacturer="Sullins Connector Solutions", Supplier Part Number 1=S9014E-04-ND
D1: library part CMP-0002946-3, "LED, Blue, SMD", Color=Blue, Digikey Part Number=732-4966-6-ND?, Manufacturer="Wurth Elektronik", Power_TotalModule=105mW, Value1=0.105W, Value2=3.2V
D2: library part CMP-0002947-3, "LED, Red, SMD", Color=Red, Digikey Part Number=732-4978-6-ND?, Manufacturer="Wurth Elektronik", Power_TotalModule=72mW, Value1=0.072W, Value2=2V
D3: library part CMP-0002892-3, "LED, Yellow, SMD", Color=yellow, Digikey Part Number=?732-4981-6-ND?, Manufacturer="Wurth Elektronik", Value1=W, Value2=2V
D4: library part CMP-0002905-2, "LED, Green, SMD", Color=Green, Digikey Part Number=732-4971-6-ND?, Manufacturer="Wurth Elektronik", Value1=W, Value2=3.2V
D5 D6: library part CMP-0860710-3, "1-channel 30 kV ESD protection diode with low capacitance (< 1pF) in 0402 package, DPY0002A (X1SON-2)", Alternate Manufacturer="Texas Instruments", Digikey Part Number=?296-51108-1-ND?, Operating Temperature Range="-40 to 125 C", Rating=Catalog
D8: library part CMP-0028822-2, "Diode, Schottky, 40 V, 2 A, AEC-Q101, SMAF", Manufacturer="Fairchild Semiconductor", Value1=2A, Value2=0.5V
FB1 FB2 FB3 FB4 FB5 FB6 FB7 FB8 FB9 FB10 FB11 FB12: library part CMP-0089995-1, "120 Ohms @ 100MHz 1 Power Line Ferrite Bead 0603 (1608 Metric) 3A 30mOhm", Digikey Part Number=490-5254-1-ND, Impedance At Frequency="120O @ 100MHz", Manufacturer=Murata, Mouser Part Number=81-BLM18KG121TN1D, Operating Temperature Range="-55°C to +125°C", Test Frequency=100MHz, Tolerance_%=25%
FID1 FID2 FID3 FID6 FID6_1 FID6_2: library part CMP-0077181-1, "Fiducial mark.  There is nothing to buy or mount.", Manufacturer=N/A
H1 H2 H3 H4 H5 H6: library part CMP-0003617-1, "Machine Screw, Round, #4-40 x 1/4, Nylon, Philips panhead", Manufacturer="B&F Fastener Supply", Supplier Part Number 1=H542-ND
H7 H8 H9 H10 H11 H12: library part CMP-0003610-1, "Standoff, Hex, 0.5\"L #4-40 Nylon", Manufacturer=Keystone, Supplier Part Number 1=36-1902C-ND
J1: library part CMP-0055471-1, "Terminal Block, 5.08 mm, 2x1, TH", Color=Green, Current_A=17.5A, Manufacturer="Phoenix Contact", Supplier Part Number 1=277-1263-ND, Voltage_V=400V
J2 J4 J6 J10 J12 J14: library part CMP-0075257-1, "Header, 2mm, 2x1, Gold, Black, TH", Color=Black, Current_A=1A, Manufacturer=Harwin, Supplier Part Number 1=952-1311-ND, Voltage_V=500V
J5: library part CMP-0075533-1, "Header, 1.27 mm, 5x2, Gold, TH", Color=Black, Manufacturer=Samtec, Supplier Part Number 1=FTSH-105-01-F-D-K-ND
J7: library part CMP-0003837-4, "Receptacle, 2.54mm, 10x2, Tin, TH", Alternate Manufacturer="Major League Electronics", Alternate PartNumber=CRD-081413-A-G, Manufacturer=Samtec, Supplier Part Number 1=SAM1204-10-ND
J8: library part CMP-0078266-4, "Receptacle, 2.54mm, 10x2, Tin, TH", Alternate Manufacturer="Major League Electronics", Alternate PartNumber=CRD-081413-A-G, Manufacturer=Samtec, Supplier Part Number 1=SAM1204-10-ND
J9: library part CMP-0075359-1, "Header, 2mm, 2x2, Gold, TH", Color=Black, Current_A=1A, Manufacturer=3M, Supplier Part Number 1=3M9188-04-ND, Voltage_V=1kV
J11: library part CMP-0054802-1, "Header, 2.54mm, 3x2, Gold, TH", Color=Black, Manufacturer="Wurth Elektronik", Supplier Part Number 1=732-5295-ND
J13: library part CMP-0075410-1, "Header, 100mil, 5x2, Gold, TH", Color=Black, Current_A=6.3A, Manufacturer=Samtec, Supplier Part Number 1=SAM1028-05-ND, Voltage_V=550V
L1: library part CMP-0089502-1, "Power Inductor (SMD), 4.7 µH, 5.1 A, Shielded, 4.5 A, XAL40xx Series, 4mm x 4mm x 3.1mm", Manufacturer=Coilcraft, Mouser Part Number=994-XAL4030-472MEC, Operating Temperature Range="to +165°C", Self Resonant Frequency=36MHz, Test Frequency=1MHz, Tolerance_%=20%
L2 L4 L5 L6: library part CMP-0077678-3, "Inductor, Shielded, Metal Composite, 470 nH, 3.6 A, 0.032 ohm, SMD", Manufacturer=MuRata, PartNumber=DFE201610E-R47M{}P2, Supplier Part Number 1=490-18109-1-ND, Value1="0.032 ohm", Value2=3.6A, ValueDisplayed=470nH
L3: library part CMP-0061150-1, "Inductor, Shielded, Composite, 2.2 uH, 3.7 A, 0.02 ohm, SMD", Manufacturer=Coilcraft, Supplier Part Number 1=994-XFL4020-222MEB, Value1="0.02 ohm", Value2=3.7A, ValueDisplayed=2.2uH
LBL1: library part CMP-0003625-1, "Thermal Transfer Printable Labels, 0.650\" W x 0.200\" H - 10,000 per roll", Manufacturer=Brady, Supplier Part Number 1=97C5133
Logo1: library part CMP-0074847-1, "FCC_disclaimer"
Logo2: library part CMP-0074769-1
Logo3: library part CMP-0074838-1, "Texas Instrument Corporate Signature"
Logo4: library part CMP-0074844-1
MK1: library part CMP-0001813-2, "Microphone, Electret Condenser, Omnidirectional, -42 dB, SMD", Manufacturer="CUI Inc.", Supplier Part Number 1=102-1719-ND
Q1: library part CMP-0000092-3, "MOSFET, P-CH, -20 V, -3.7 A, SOT-23", Alternate Manufacturer=None, Digikey Part Number=SI2323DS-T1-E3CT-ND, Manufacturer=Vishay-Siliconix, Value1=0.03, Value2="12.5 nC"
Q2 Q3 Q4 Q5: library part CMP-0089424-1, "N-Channel 30V 270mA (Ta) 330mW (Ta) Surface Mount SC-70-3 (SOT323)", Digikey Part Number=NTS4001NT1GOSCT-ND, Drain To Source Breakdown Voltage=30V, Input Capacitace At Vds="20pF @ 5V", Manufacturer="On Semiconductor", Mouser Part Number=863-NTS4001NT1G, Operating Temperature Range="-55°C to +150°C", Power_W=330mW, Pulse Drain Current=800mA, Typ Forward Diode Voltage=0.65V
R1 R86 R87 R88 R95 R151: library part CMP-0023343-2, "RES, 0, 1%, 0.1 W, AEC-Q200 Grade 0, 0603", Manufacturer="Stackpole Electronics Inc", Power_W=100mW, Supplier Part Number 1=RMCF0603ZT0R00CT-ND, TempCo=ppm/C, Tolerance_%=1%, Value2=0.1W, Value_Code=0
R2 R3 R42 R100 R101 R108 R112 R123: library part CMP-0023343-3, "RES, 0, 1%, 0.1 W, AEC-Q200 Grade 0, 0603", Manufacturer="Stackpole Electronics Inc", Power_W=100mW, Supplier Part Number 1=RMCF0603ZT0R00CT-ND, TempCo=ppm/C, Tolerance_%=1%, Value2=0.1W, Value_Code=0
R4: library part CMP-0026993-1, "RES, 100, 5%, 0.1 W, AEC-Q200 Grade 0, 0402", Manufacturer=Panasonic, Power_W=100mW, Supplier Part Number 1=P100JCT-ND, TempCo="200 ppm/C", Tolerance_%=5%, Value2=0.1W, Value_Code=100R, ValueDisplayed=100
R5 R13 R15 R18 R19 R20 R33 R34 R43 R44 R77 R111 R117 R122 R129 R131 R132 R161 R170 R187: library part CMP-0078779-1, "RES, 10.0 k, 1%, 0.2 W, AEC-Q200 Grade 0, 0402", Manufacturer=Panasonic, Power_W=200mW, Supplier Part Number 1=P17230CT-ND, TempCo="100 ppm/C", Tolerance_%=1%, Value2=0.2W, Value_Code=10k0, ValueDisplayed=10.0k
R6 R11 R35 R36 R37 R38 R39 R40: library part CMP-0026659-2, "RES, 100 k, 1%, 0.1 W, 0402", Manufacturer=Panasonic, Power_W=100mW, Supplier Part Number 1=P100KLCT-ND, TempCo="100 ppm/C", Tolerance_%=1%, Value2=0.1W, Value_Code=100k
R7 R8 R12 R17 R21 R23 R24 R30 R31 R32 R45 R46 R47 R48 R49 R50 R51 R52 R53 R54 R58 R59 R60 R65 R66 R70 R71 R73 R74 R75 R78 R79 R80 R81 R82 R83 R84 R90 R115 R119 R125 R126 R130 R136 R138 R139 R140 R143 R144 R153 R154 R155 R156 R157 R158 R159 R160 R162 R169 R171 R174 R175 R176 R177 R178 R179 R180 R181 R184: library part CMP-0027004-2, "RES, 0, 5%, 0.063 W, 0402", Manufacturer="Yageo America", Power_W=63mW, Supplier Part Number 1=311-0.0JRCT-ND, TempCo="200 ppm/C", Tolerance_%=5%, Value2=0.063W, Value_Code=0000, ValueDisplayed=0
R9 R10: library part CMP-0026746-1, "RES, 232 k, 1%, 0.063 W, 0402", Manufacturer="Samsung Electro-Mechanics", Power_W=63mW, Supplier Part Number 1=1276-4230-1-ND, TempCo="100 ppm/C", Tolerance_%=1%, Value2=0.063W, Value_Code=232k
R14: library part CMP-0074667-1, "RES, 2.20 k, 0.1%, 0.0625 W, AEC-Q200 Grade 0, 0402", Manufacturer=Panasonic, Power_W=62.5mW, Supplier Part Number 1=P2.2KDCCT-ND, TempCo="25 ppm/C", Tolerance_%=0.1%, Value2=0.0625W, Value_Code=2k20, ValueDisplayed=2.20k
R16 R22 R96 R97 R98 R116 R118 R163 R164 R165 R166 R167 R168: library part CMP-0027293-2, "RES, 100 k, 1%, 0.05 W, 0201", Manufacturer="Yageo America", Power_W=50mW, Supplier Part Number 1=311-100KMCT-ND, TempCo="200 ppm/C", Tolerance_%=1%, Value2=0.05W, Value_Code=100k
R25 R26 R27 R28 R29 R121: library part CMP-0026738-1, "RES, 49.9, 1%, 0.063 W, 0402", Manufacturer="Yageo America", Power_W=63mW, Supplier Part Number 1=311-49.9LRCT-ND, TempCo="100 ppm/C", Tolerance_%=1%, Value2=0.063W, Value_Code=49R9, ValueDisplayed=49.9
R41: library part CMP-0026822-3, "RES, 0, 5%, 0.063 W, AEC-Q200 Grade 0, 0402", Manufacturer=Vishay-Dale, PartNumber=CRCW04020000Z0ED, Power_W=63mW, Supplier Part Number 1=541-0.0JCT-ND, TempCo="200 ppm/C", Tolerance_%=5%, Value2=0.063W, Value_Code=0000, ValueDisplayed=0
R55 R56 R57 R89 R105 R113 R172 R173 R182 R183 R185 R186: library part CMP-0026071-3, "RES, 1.00 k, 1%, 0.063 W, AEC-Q200 Grade 0, 0402", Manufacturer=Vishay-Dale, Power_W=63mW, Supplier Part Number 1=541-1.0KAVCT-ND?, TempCo="100 ppm/C", Tolerance_%=1%, Value2=0.063W, Value_Code=1k00, ValueDisplayed=1.00k
R61 R106: library part CMP-0026684-1, "RES, 240, 1%, 0.1 W, AEC-Q200 Grade 0, 0402", Manufacturer=Panasonic, Power_W=100mW, Supplier Part Number 1=P240LCT-ND, TempCo="100 ppm/C", Tolerance_%=1%, Value2=0.1W, Value_Code=240R, ValueDisplayed=240
R62: library part CMP-0022448-4, "RES, 49.9, 1%, 0.1 W, AEC-Q200 Grade 0, 0603", Manufacturer=Vishay-Dale, Power_W=100mW, Supplier Part Number 1=541-49.9HCT-ND, TempCo="100 ppm/C", Tolerance_%=1%, Value2=0.1W, Value_Code=49R9, ValueDisplayed=49.9
R63: library part CMP-0026757-1, "RES, 1.00 M, 1%, 0.063 W, AEC-Q200 Grade 0, 0402", Manufacturer="Stackpole Electronics Inc", Power_W=63mW, Supplier Part Number 1=RMCF0402FT1M00CT-ND, TempCo="100 ppm/C", Tolerance_%=1%, Value2=0.063W, Value_Code=1M00, ValueDisplayed=1.00M
R64: library part CMP-0016519-2, "RES, 0.04, 1%, 1 W, 2010", Manufacturer="Stackpole Electronics Inc", Power_W=1W, Supplier Part Number 1=CSRN2010FK40L0CT-ND, TempCo="250 ppm/C", Tolerance_%=1%, Value_Code=R040, ValueDisplayed=0.04
R67: library part CMP-0023028-4, "RES, 324 k, 1%, 0.1 W, 0603", Manufacturer=Yageo, Power_W=100mW, Supplier Part Number 1=311-324KHRCT-ND, TempCo="100 ppm/C", Tolerance_%=1%, Value2=0.1W, Value_Code=324k
R68: library part CMP-0022261-4, "RES, 28.7 k, 1%, 0.1 W, AEC-Q200 Grade 0, 0603", Manufacturer=Vishay-Dale, Power_W=100mW, Supplier Part Number 1=541-28.7KHCT-ND, TempCo="100 ppm/C", Tolerance_%=1%, Value2=0.1W, Value_Code=28k7, ValueDisplayed=28.7k
R69: library part CMP-0027004-2, "RES, 0, 5%, 0.063 W, 0402", Manufacturer="Yageo America", Power_W=63mW, Supplier Part Number 1=311-0.0JRCT-ND, TempCo="200 ppm/C", Tolerance_%=5%, Value2=0.063W, Value_Code=0000
R72: library part CMP-0022052-4, "RES, 147 k, 1%, 0.1 W, AEC-Q200 Grade 0, 0603", Manufacturer=Vishay-Dale, Power_W=100mW, Supplier Part Number 1=541-147KHCT-ND, TempCo="100 ppm/C", Tolerance_%=1%, Value2=0.1W, Value_Code=147k
R76 R85 R120: library part CMP-0026700-1, "RES, 4.70 k, 1%, 0.1 W, 0402", Manufacturer=Panasonic, Power_W=100mW, Supplier Part Number 1=P4.70KLCT-ND, TempCo="100 ppm/C", Tolerance_%=1%, Value2=0.1W, Value_Code=4k70, ValueDisplayed=4.70k
R91 R137 R152: library part CMP-0019096-2, "RES, 100 k, 0.5%, 0.1 W, 0805", Manufacturer="Susumu Co Ltd", Power_W=100mW, Supplier Part Number 1=RR12P100KDCT-ND, TempCo="25 ppm/C", Tolerance_%=0.5%, Value2=0.1W, Value_Code=100k
R92 R102 R103 R145 R146: library part CMP-0026635-1, "RES, 0.33, 1%, 0.125 W, 0402", Manufacturer=Panasonic, Power_W=125mW, Supplier Part Number 1=P.33AKCT-ND, TempCo="250 ppm/C", Tolerance_%=1%, Value2=0.125W, Value_Code=R330, ValueDisplayed=0.33
R93 R107 R141 R148: library part CMP-0025950-3, "RES, 100 k, 1%, 0.063 W, AEC-Q200 Grade 0, 0402", Manufacturer=Vishay-Dale, Power_W=63mW, Supplier Part Number 1=541-100KLCT-ND, TempCo="100 ppm/C", Tolerance_%=1%, Value2=0.063W, Value_Code=100k
R94: library part CMP-0026393-2, "RES, 475 k, 1%, 0.063 W, AEC-Q200 Grade 0, 0402", Manufacturer=Vishay-Dale, Power_W=63mW, Supplier Part Number 1=541-475KLCT-ND, TempCo="100 ppm/C", Tolerance_%=1%, Value2=0.063W, Value_Code=475k
R99: library part CMP-0025986-3, "RES, 124 k, 1%, 0.063 W, AEC-Q200 Grade 0, 0402", Manufacturer=Vishay-Dale, Power_W=63mW, Supplier Part Number 1=71-CRCW0402-124K-E3, TempCo="100 ppm/C", Tolerance_%=1%, Value2=0.063W, Value_Code=124k
R104: library part CMP-0026071-3, "RES, 1.00 k, 1%, 0.063 W, AEC-Q200 Grade 0, 0402", Manufacturer=Vishay-Dale, Power_W=63mW, Supplier Part Number 1=541-1.0KAVCT-ND??, TempCo="100 ppm/C", Tolerance_%=1%, Value2=0.063W, Value_Code=1k00, ValueDisplayed=1.00k
R109: library part CMP-0027754-1, "RES, 511 k, 1%, 0.05 W, 0201", Manufacturer="Yageo America", Power_W=50mW, Supplier Part Number 1=YAG2715CT-ND, TempCo="200 ppm/C", Tolerance_%=1%, Value2=0.05W, Value_Code=511k
R110: library part CMP-0023318-5, "RES, 91.0 k, 1%, 0.1 W, 0603", Manufacturer=Yageo, Power_W=100mW, Supplier Part Number 1=311-91.0KHRCT-ND, TempCo="100 ppm/C", Tolerance_%=1%, Value2=0.1W, Value_Code=91k0, ValueDisplayed=91.0k
R114: library part CMP-0022356-2, "RES, 36.5 k, 1%, 0.1 W, 0603", Manufacturer=Vishay-Dale, Power_W=100mW, Supplier Part Number 1=541-36.5KHCT-ND, TempCo="100 ppm/C", Tolerance_%=1%, Value2=0.1W, Value_Code=36k5, ValueDisplayed=36.5k
R124 R134 R150: library part CMP-0023339-3, "RES, 0.02, 1%, 0.1 W, AEC-Q200 Grade 0, 0603", Manufacturer="Yageo America", Power_W=100mW, Supplier Part Number 1=311-.02QCT-ND, TempCo="1500 ppm/C", Tolerance_%=1%, Value2=0.1W, Value_Code=R020, ValueDisplayed=0.02
R127 R128: library part CMP-0026815-1, "RES, 100 k, 0.1%, 0.063 W, 0402", Manufacturer="Susumu Co Ltd", Power_W=63mW, Supplier Part Number 1=RG10P100KBCT-ND, TempCo="25 ppm/C", Tolerance_%=0.1%, Value2=0.063W, Value_Code=100k
R133: library part CMP-0026825-5, "RES, 10 k, 5%, 0.063 W, AEC-Q200 Grade 0, 0402", Manufacturer=Vishay-Dale, Power_W=63mW, Supplier Part Number 1=541-10KAVCT-ND?, TempCo="200 ppm/C", Tolerance_%=5%, Value2=0.063W, Value_Code=10k0, ValueDisplayed=10k
R135 R149: library part CMP-0027891-1, "RES, 82.5 k, 1%, 0.05 W, 0201", Manufacturer="Yageo America", Power_W=50mW, Supplier Part Number 1=YAG2815CT-ND, TempCo="200 ppm/C", Tolerance_%=1%, Value2=0.05W, Value_Code=82k5, ValueDisplayed=82.5k
R142: library part CMP-0026574-2, "RES, 82.5 k, 1%, 0.063 W, AEC-Q200 Grade 0, 0402", Manufacturer=Vishay-Dale, Power_W=63mW, Supplier Part Number 1=541-82.5KLCT-ND, TempCo="100 ppm/C", Tolerance_%=1%, Value2=0.063W, Value_Code=82k5, ValueDisplayed=82.5k
R147: library part CMP-0026158-2, "RES, 200 k, 1%, 0.063 W, AEC-Q200 Grade 0, 0402", Manufacturer=Vishay-Dale, Power_W=63mW, Supplier Part Number 1=541-200KLCT-ND, TempCo="100 ppm/C", Tolerance_%=1%, Value2=0.063W, Value_Code=200k
SW1 SW2: library part CMP-0089991-1, "Tactile Switch SPST-NO Top Actuated Surface Mount", Coil Resistance_ohm=100mO, Contact Current Rating=50mA, Digikey Part Number=732-6995-1-ND, Manufacturer="Wurth Electronics", Mouser Part Number=710-430152070826, Operating Force=260gf, Operating Temperature Range="-40°C to +85°C"
SW3: library part CMP-0002165-2, "DIP Switch, SPST, 3Pos, Slide, SMT", CurrentRating_mA=100A, Manufacturer="Copal Electronics", Supplier Part Number 1=563-1194-1-ND
TP4: library part CMP-0055137-1, "Test Point, Miniature, Red, TH", Color=Red, Manufacturer=Keystone, PartNumber=5000, Supplier Part Number 1=36-5000-ND
U1: library part CMP-0085201-1, "SimpleLink Wi-FI and Internet-of-Things Dual Band Module Solution, a Single-Chip Wireless MCU, MON0063A (QFM-63)", Alternate Manufacturer="Texas Instruments"
U2: library part CMP-0042983-1, "3.2 W Mono Class-D With Auto-Recovering Short-Circuit Protection, -40 to 85 degC, 9-pin BGA (YFF9), Green (RoHS & no Sb/Br)", Manufacturer="Texas Instruments", Output Power(W)=3.24, Supply Max(Max)(Volt)=5.5, Supply Min(Min)(Volt)=2.5
U3 U5: library part CMP-0085652-1, "+/-6V, Low IQ Ideal Diode with Input Polarity Protection, DCK0006A (SOT-SC70-6)", Alternate Manufacturer="Texas Instruments", Alternate PartNumber=LM66100DCKR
